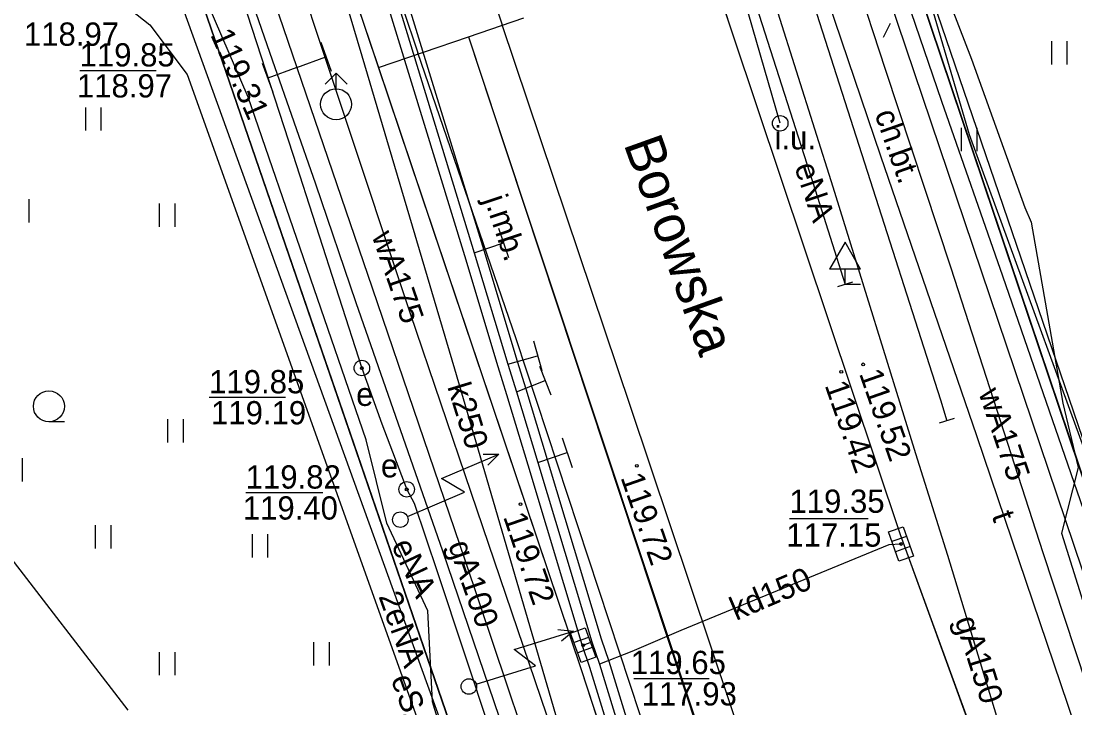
# Model space of a CAD drawing. Extents: x 6432121 to 6432331, y 5662538 to 5662686.
# Drawn here: x 6432243.57 to 6432277.55, y 5662605.46 to 5662627.61 of the extents above; entities that cross this region are included whole.
import ezdxf

# ---------------------------------------------------------------- set-up
doc = ezdxf.new("R2010")
doc.units = 0
for name, color, linetype in [('Warstwa 1', 7, 'Continuous'), ('Warstwa 10', 7, 'Continuous'), ('Warstwa 11', 7, 'Continuous'), ('Warstwa 12', 7, 'Continuous'), ('Warstwa 13', 7, 'Continuous'), ('Warstwa 14', 7, 'Continuous'), ('Warstwa 15', 7, 'Continuous'), ('Warstwa 19', 7, 'Continuous'), ('Warstwa 20', 7, 'Continuous'), ('Warstwa 24', 7, 'Continuous'), ('Warstwa 25', 7, 'Continuous'), ('Warstwa 31', 7, 'Continuous'), ('Warstwa 37', 7, 'Continuous'), ('Warstwa 4', 7, 'Continuous'), ('Warstwa 40', 7, 'Continuous'), ('Warstwa 5', 7, 'Continuous'), ('Warstwa 6', 7, 'Continuous'), ('Warstwa 61', 7, 'Continuous'), ('Warstwa 8', 7, 'Continuous'), ('Warstwa 9', 7, 'Continuous')]:
    doc.layers.add(name, color=color, linetype=linetype)

msp = doc.modelspace()

# ---------------------------------------------------------------- linework, layer by layer
at = {"layer": 'Warstwa 1'}
for p, q in [((6432267.75, 5662642.76), (6432287.64, 5662583.69)), ((6432267.75, 5662642.76), (6432287.64, 5662583.69)), ((6432246.69, 5662636.13), (6432263.163, 5662588.197)), ((6432246.69, 5662636.13), (6432263.163, 5662588.197))]:
    msp.add_line(p, q, dxfattribs=at)
for centre in [(6432255.8, 5662611.53), (6432258.012, 5662606.151)]:
    msp.add_circle(centre, 0.25, dxfattribs=at)
at = {"layer": 'Warstwa 10'}
msp.add_lwpolyline([(6432244.8, 5662632.18), (6432245.33, 5662629.54), (6432245.69, 5662629.01), (6432246.09, 5662628.79), (6432247.73, 5662627.49), (6432248.93, 5662625.88), (6432257.3, 5662602.44), (6432259.59, 5662595.58)], dxfattribs=at)
at = {"layer": 'Warstwa 12'}
for points in [[(6432260.149, 5662593.584), (6432259.505, 5662597.442), (6432258.113, 5662602.229), (6432246.261, 5662635.045), (6432242.6, 5662639.91), (6432237.105, 5662644.467), (6432235.235, 5662651.91), (6432228.3, 5662671.335), (6432227.148, 5662676.149), (6432227.614, 5662677.443), (6432228.191, 5662677.996), (6432231.551, 5662678.816), (6432233.235, 5662681.053)], [(6432259.267, 5662681.053), (6432259.329, 5662671.143), (6432259.331, 5662662.919), (6432260.078, 5662660.682), (6432263.877, 5662649.208), (6432267.527, 5662638.022), (6432271.438, 5662626.054), (6432273.548, 5662619.652), (6432276.516, 5662610.473), (6432279.664, 5662600.926), (6432282.613, 5662591.736), (6432284.976, 5662585.268), (6432286.395, 5662580.459), (6432288.268, 5662574.665)], [(6432288.269, 5662573.47), (6432290.18, 5662576.365), (6432289.651, 5662577.89), (6432283.657, 5662595.089), (6432278.636, 5662609.529), (6432275.228, 5662619.384), (6432273.259, 5662625.008), (6432269.06, 5662637.307), (6432265.455, 5662647.676), (6432262.131, 5662657.28), (6432261.494, 5662659.216), (6432262.228, 5662660.626), (6432262.598, 5662661.472), (6432263.21, 5662662.431), (6432263.592, 5662662.793), (6432265.636, 5662665.038), (6432264.282, 5662671.637), (6432263.631, 5662675.181), (6432263.032, 5662678.117), (6432262.911, 5662681.053)], [(6432251.161, 5662678.636), (6432251.195, 5662678.505), (6432250.722, 5662667.538), (6432250.449, 5662664.161), (6432250.95, 5662660.785), (6432251.946, 5662652.429), (6432252.859, 5662647.409), (6432253.435, 5662643.141), (6432255.033, 5662633.254), (6432255.483, 5662630.016), (6432258.492, 5662620.223), (6432259.57, 5662616.642), (6432259.85, 5662615.749), (6432260.538, 5662613.47), (6432262.28, 5662607.688), (6432262.524, 5662606.965), (6432264.736, 5662599.765)], [(6432264.124, 5662599.577), (6432261.914, 5662606.769), (6432261.67, 5662607.494), (6432259.926, 5662613.286), (6432259.238, 5662615.561), (6432258.958, 5662616.454), (6432257.88, 5662620.037), (6432254.857, 5662629.878), (6432254.401, 5662633.158), (6432252.801, 5662643.047), (6432252.227, 5662647.309), (6432251.312, 5662652.333), (6432250.316, 5662660.701), (6432249.805, 5662664.139), (6432250.084, 5662667.578), (6432250.551, 5662678.439), (6432250.541, 5662678.478)], [(6432258.356, 5662662.998), (6432258.39, 5662658.398), (6432260.508, 5662651.738), (6432262.768, 5662644.481), (6432265.197, 5662636.781), (6432267.384, 5662629.75), (6432269.748, 5662622.257), (6432272.462, 5662613.493), (6432273.441, 5662610.386), (6432276.081, 5662601.737), (6432278.642, 5662593.628), (6432281.263, 5662585.188), (6432283.543, 5662577.76), (6432283.852, 5662577.022), (6432284.284, 5662575.255)], [(6432261.338, 5662662.021), (6432260.831, 5662661.256), (6432261.33, 5662655.003), (6432261.566, 5662651.833), (6432262.397, 5662649.473), (6432263.18, 5662647.177), (6432265.745, 5662639.575), (6432268.331, 5662631.988), (6432271.28, 5662623.264), (6432274.385, 5662614.242), (6432277.778, 5662604.216), (6432280.796, 5662595.387), (6432284.518, 5662584.444), (6432287.071, 5662576.95), (6432288.269, 5662573.47)], [(6432244.451, 5662661.055), (6432244.51, 5662660.562), (6432244.747, 5662659.597), (6432247.148, 5662651.498), (6432250.159, 5662641.297), (6432254.564, 5662626.481), (6432257.548, 5662616.394), (6432260.807, 5662605.248), (6432262.453, 5662599.664), (6432266.272, 5662586.802), (6432268.265, 5662580.011), (6432268.423, 5662579.446)], [(6432243.958, 5662654.289), (6432246.621, 5662646.365), (6432250.032, 5662636.381), (6432251.998, 5662630.56), (6432253.864, 5662624.956), (6432256.122, 5662618.174), (6432258.071, 5662612.417), (6432261.076, 5662603.597), (6432261.907, 5662601.278), (6432263.382, 5662596.576), (6432264.52, 5662593.503), (6432265.328, 5662591.162), (6432268.156, 5662582.752), (6432268.733, 5662580.715)], [(6432243.16, 5662653.357), (6432252.465, 5662626.114), (6432254.893, 5662619.007), (6432257.883, 5662610.233), (6432261.03, 5662600.869), (6432263.754, 5662592.896), (6432267.107, 5662583.22), (6432267.857, 5662579.356), (6432269.061, 5662572.854)], [(6432294.644, 5662569.974), (6432292.199, 5662571.213), (6432291.73, 5662571.359), (6432291.554, 5662571.691), (6432290.843, 5662575.72), (6432287.011, 5662587.057), (6432285.41, 5662591.097), (6432281.352, 5662603.627), (6432279.346, 5662609.722), (6432279.211, 5662610.184), (6432279.026, 5662610.616), (6432274.158, 5662623.936), (6432272.237, 5662630.449), (6432265.984, 5662647.596), (6432266.37, 5662648.378)], [(6432291.73, 5662571.359), (6432291.68, 5662571.75), (6432289.74, 5662579), (6432288.94, 5662582.19), (6432279.33, 5662609.79), (6432279.211, 5662610.184), (6432278.94, 5662610.85), (6432266.32, 5662647.75), (6432266.37, 5662648.378)], [(6432268.05, 5662624.31), (6432264.48, 5662636.66)], [(6432244.8, 5662632.18), (6432245.33, 5662629.54), (6432245.69, 5662629.01), (6432246.09, 5662628.79), (6432247.73, 5662627.49), (6432248.93, 5662625.88), (6432257.3, 5662602.44), (6432259.59, 5662595.58)], [(6432268.23, 5662630.953), (6432270.582, 5662623.607), (6432273.222, 5662615.395), (6432273.419, 5662614.713)], [(6432266.467, 5662630.62), (6432269.173, 5662622.164), (6432270.14, 5662619.109)], [(6432249.61, 5662630.185), (6432250.286, 5662629.633), (6432252.331, 5662623.317), (6432254.562, 5662616.419), (6432255.202, 5662614.617), (6432256.008, 5662612.508), (6432256.249, 5662612.065), (6432256.997, 5662609.824), (6432258.713, 5662604.681), (6432261.287, 5662596.72), (6432264.864, 5662586.606), (6432264.777, 5662586.057)], [(6432264.921, 5662586.356), (6432264.864, 5662586.606), (6432260.124, 5662594.894), (6432256.835, 5662605.655), (6432256.691, 5662608.587), (6432255.365, 5662611.413), (6432254.697, 5662614.101), (6432250.901, 5662625.148), (6432249.199, 5662629.099), (6432249.05, 5662629.25)], [(6432273.378, 5662628.56), (6432274.214, 5662626.373), (6432275.936, 5662621.592), (6432276.137, 5662621.121), (6432277.158, 5662615.29), (6432277.656, 5662613.21), (6432277.121, 5662611.091), (6432279.065, 5662604.892), (6432281.714, 5662603.797), (6432281.489, 5662600.828), (6432283.129, 5662594.282), (6432283.903, 5662591.502), (6432284.529, 5662588.89)], [(6432271.946, 5662610.746), (6432271.557, 5662610.723), (6432264.842, 5662607.958), (6432263.268, 5662607.285), (6432262.219, 5662606.867)], [(6432261.697, 5662607.486), (6432261.975, 5662607.591)]]:
    msp.add_lwpolyline(points, dxfattribs=at)
at = {"layer": 'Warstwa 14'}
for p, q in [((6432245.464, 5662626.018), (6432247.927, 5662626.018)), ((6432249.641, 5662615.479), (6432252.104, 5662615.479)), ((6432250.822, 5662612.408), (6432253.307, 5662612.408)), ((6432268.354, 5662611.564), (6432270.891, 5662611.564)), ((6432263.331, 5662606.408), (6432265.757, 5662606.408))]:
    msp.add_line(p, q, dxfattribs=at)
for centre in [(6432254.562, 5662616.419), (6432254.562, 5662616.419), (6432256.008, 5662612.508), (6432256.008, 5662612.508), (6432271.946, 5662610.746), (6432271.946, 5662610.746), (6432261.697, 5662607.486), (6432261.697, 5662607.486)]:
    msp.add_circle(centre, 0.045, dxfattribs=at)
at = {"layer": 'Warstwa 19'}
for p, q in [((6432253.234, 5662626.926), (6432253.576, 5662625.986)), ((6432251.699, 5662625.3), (6432251.354, 5662626.238)), ((6432252.465, 5662626.114), (6432253.405, 5662626.456)), ((6432252.465, 5662626.114), (6432251.526, 5662625.769)), ((6432258.965, 5662620.932), (6432259.295, 5662619.988)), ((6432258.186, 5662620.13), (6432259.13, 5662620.46)), ((6432260.092, 5662617.3), (6432260.362, 5662616.337)), ((6432259.264, 5662616.548), (6432260.227, 5662616.818)), ((6432260.293, 5662616.485), (6432260.657, 5662615.554)), ((6432259.544, 5662615.655), (6432260.475, 5662616.02)), ((6432261.024, 5662614.167), (6432261.339, 5662613.218)), ((6432260.232, 5662613.378), (6432261.181, 5662613.693))]:
    msp.add_line(p, q, dxfattribs=at)
at = {"layer": 'Warstwa 20'}
for p, q in [((6432270.378, 5662619.185), (6432269.902, 5662619.033)), ((6432273.657, 5662614.789), (6432273.181, 5662614.637))]:
    msp.add_line(p, q, dxfattribs=at)
at = {"layer": 'Warstwa 24'}
msp.add_circle((6432268.05, 5662624.31), 0.25, dxfattribs=at)
at = {"layer": 'Warstwa 25'}
for centre in [(6432270.021, 5662616.3), (6432270.727, 5662616.538), (6432263.43, 5662613.264), (6432259.679, 5662612.028)]:
    msp.add_circle(centre, 0.045, dxfattribs=at)
at = {"layer": 'Warstwa 31'}
for p, q in [((6432270.64, 5662619.609), (6432270.14, 5662620.475)), ((6432270.14, 5662619.109), (6432270.14, 5662619.609)), ((6432270.64, 5662619.109), (6432270.14, 5662619.109))]:
    msp.add_line(p, q, dxfattribs=at)
for points in [[(6432270.14, 5662620.475), (6432269.64, 5662619.609)], [(6432270.64, 5662619.609), (6432269.64, 5662619.609)]]:
    msp.add_lwpolyline(points, dxfattribs=at)
at = {"layer": 'Warstwa 37'}
for points in [[(6432249.116, 5662650.415), (6432249.248, 5662649.722), (6432249.38, 5662649.03), (6432250.17, 5662645.84), (6432251.85, 5662640.08), (6432254.2, 5662633.06), (6432255.4, 5662629.47), (6432256.37, 5662626.58)], [(6432252.027, 5662650.548), (6432252.197, 5662649.798), (6432252.37, 5662649.049), (6432252.548, 5662648.301), (6432252.73, 5662647.555), (6432252.916, 5662646.809), (6432253.106, 5662646.064), (6432253.3, 5662645.32), (6432253.426, 5662644.858), (6432253.554, 5662644.396), (6432253.685, 5662643.935), (6432253.817, 5662643.474), (6432253.952, 5662643.014), (6432254.088, 5662642.555), (6432254.227, 5662642.096), (6432254.367, 5662641.638), (6432254.51, 5662641.18), (6432256.27, 5662635.89), (6432257.45, 5662632.38), (6432259.09, 5662627.49)], [(6432270.98, 5662592.032), (6432263.223, 5662615.178), (6432259.09, 5662627.49)], [(6432268.199, 5662591.096), (6432259.533, 5662617.358), (6432256.37, 5662626.58)]]:
    msp.add_lwpolyline(points, dxfattribs=at)
at = {"layer": 'Warstwa 4'}
for p, q in [((6432272.125, 5662610.993), (6432271.652, 5662610.829)), ((6432272.24, 5662610.663), (6432271.767, 5662610.499)), ((6432261.873, 5662607.735), (6432261.403, 5662607.566)), ((6432261.991, 5662607.406), (6432261.521, 5662607.237))]:
    msp.add_line(p, q, dxfattribs=at)
for points in [[(6432271.594, 5662627.529), (6432271.37, 5662627.082)], [(6432253.375, 5662625.57), (6432253.729, 5662625.924)], [(6432254.083, 5662625.57), (6432253.729, 5662625.924)], [(6432253.729, 5662625.424), (6432253.729, 5662625.924)]]:
    msp.add_lwpolyline(points, dxfattribs=at)
for points in [[(6432272.018, 5662611.3), (6432272.346, 5662610.355), (6432271.874, 5662610.192), (6432271.546, 5662611.137)], [(6432261.764, 5662608.041), (6432262.101, 5662607.1), (6432261.63, 5662606.931), (6432261.293, 5662607.872)]]:
    msp.add_lwpolyline(points, close=True, dxfattribs=at)
for centre, radius in [((6432253.729, 5662624.924), 0.5), ((6432254.562, 5662616.419), 0.25), ((6432256.008, 5662612.508), 0.25)]:
    msp.add_circle(centre, radius, dxfattribs=at)
at = {"layer": 'Warstwa 40'}
for points in [[(6432256.03, 5662611.628), (6432257.869, 5662612.414), (6432257.134, 5662612.861), (6432258.973, 5662613.647)], [(6432258.473, 5662613.647), (6432258.973, 5662613.647), (6432258.627, 5662613.287)], [(6432258.251, 5662606.226), (6432260.159, 5662606.823), (6432259.473, 5662607.342), (6432261.382, 5662607.939)], [(6432260.884, 5662607.989), (6432261.382, 5662607.939), (6432261.001, 5662607.615)]]:
    msp.add_lwpolyline(points, dxfattribs=at)
for centre in [(6432255.8, 5662611.53), (6432258.012, 5662606.151)]:
    msp.add_circle(centre, 0.25, dxfattribs=at)
at = {"layer": 'Warstwa 5'}
for p, q in [((6432271.072, 5662629.787), (6432281.622, 5662598.544)), ((6432250.664, 5662629.247), (6432251.67, 5662626.36)), ((6432276.805, 5662626.204), (6432276.805, 5662626.954)), ((6432277.305, 5662626.204), (6432277.305, 5662626.954)), ((6432251.67, 5662626.36), (6432253.062, 5662622.363)), ((6432245.657, 5662624.074), (6432245.657, 5662624.824)), ((6432246.157, 5662624.074), (6432246.157, 5662624.824)), ((6432273.899, 5662623.41), (6432273.899, 5662624.16)), ((6432274.399, 5662623.41), (6432274.399, 5662624.16)), ((6432253.062, 5662622.363), (6432254.367, 5662618.531)), ((6432243.834, 5662621.112), (6432243.834, 5662621.862)), ((6432248.038, 5662620.972), (6432248.038, 5662621.722)), ((6432248.538, 5662620.972), (6432248.538, 5662621.722)), ((6432254.367, 5662618.531), (6432257.161, 5662610.526)), ((6432248.306, 5662614.018), (6432248.306, 5662614.768)), ((6432248.806, 5662614.018), (6432248.806, 5662614.768)), ((6432243.622, 5662612.761), (6432243.622, 5662613.511)), ((6432241.266, 5662612.847), (6432247.012, 5662605.394)), ((6432245.977, 5662610.602), (6432245.977, 5662611.352)), ((6432246.477, 5662610.602), (6432246.477, 5662611.352)), ((6432251.032, 5662610.314), (6432251.032, 5662611.064)), ((6432251.532, 5662610.314), (6432251.532, 5662611.064)), ((6432257.161, 5662610.526), (6432259.889, 5662602.532)), ((6432253.013, 5662606.826), (6432253.013, 5662607.576)), ((6432253.513, 5662606.826), (6432253.513, 5662607.576)), ((6432248.039, 5662606.514), (6432248.039, 5662607.264)), ((6432248.539, 5662606.514), (6432248.539, 5662607.264))]:
    msp.add_line(p, q, dxfattribs=at)
at = {"layer": 'Warstwa 6'}
msp.add_line((6432244.97, 5662614.686), (6432244.47, 5662614.686), dxfattribs=at)
for points in [[(6432278.892, 5662645.679), (6432279.29, 5662646.39), (6432267.75, 5662642.76), (6432287.64, 5662583.69), (6432294.025, 5662578.332), (6432295.024, 5662576.599), (6432295.196, 5662575.127), (6432301.46, 5662572.69), (6432295.88, 5662579.43), (6432289.26, 5662614.9)], [(6432259.074, 5662585.787), (6432263.163, 5662588.197), (6432246.69, 5662636.13), (6432228.29, 5662630.34), (6432193.86, 5662619.79), (6432180.9, 5662615.82)]]:
    msp.add_lwpolyline(points, close=True, dxfattribs=at)
for points in [[(6432295.199, 5662556.053), (6432289.811, 5662577.223), (6432287.64, 5662583.69), (6432267.75, 5662642.76), (6432246.69, 5662636.13), (6432263.163, 5662588.197), (6432269.007, 5662560.534), (6432269.756, 5662556.053)], [(6432261.53, 5662642.45), (6432261.725, 5662641.888), (6432263.054, 5662637.661), (6432266.526, 5662627.159), (6432271.921, 5662611.052), (6432274.366, 5662604.334), (6432277.03, 5662595.697), (6432280.318, 5662586.138), (6432281.64, 5662582.902)], [(6432253.68, 5662630.32), (6432261.638, 5662606.697), (6432266.51, 5662591.804), (6432267.797, 5662587.848)], [(6432257.996, 5662627.099), (6432261.912, 5662615.276), (6432267.276, 5662599.098), (6432269.793, 5662591.641)]]:
    msp.add_lwpolyline(points, dxfattribs=at)
msp.add_circle((6432244.47, 5662615.186), 0.5, dxfattribs=at)
at = {"layer": 'Warstwa 61'}
msp.add_lwpolyline([(6432250.819, 5662681.053), (6432250.821, 5662679.711), (6432250.716, 5662679.086), (6432250.873, 5662678.472), (6432250.403, 5662667.558), (6432250.127, 5662664.15), (6432250.633, 5662660.743), (6432251.629, 5662652.381), (6432252.543, 5662647.359), (6432253.118, 5662643.094), (6432254.717, 5662633.206), (6432255.17, 5662629.947), (6432255.2, 5662629.93), (6432258.186, 5662620.13), (6432259.264, 5662616.548), (6432259.544, 5662615.655), (6432260.232, 5662613.378), (6432261.975, 5662607.591), (6432262.219, 5662606.867), (6432264.43, 5662599.671)], dxfattribs=at)
at = {"layer": 'Warstwa 8'}
for p, q in [((6432253.68, 5662630.32), (6432255.099, 5662626.107)), ((6432266.179, 5662628.209), (6432266.526, 5662627.159)), ((6432257.996, 5662627.099), (6432259.78, 5662627.71)), ((6432257.996, 5662627.099), (6432259.78, 5662627.71)), ((6432255.099, 5662626.107), (6432257.996, 5662627.099)), ((6432255.099, 5662626.107), (6432257.996, 5662627.099)), ((6432257.996, 5662627.099), (6432258.72, 5662624.914)), ((6432257.996, 5662627.099), (6432258.72, 5662624.914)), ((6432266.526, 5662627.159), (6432271.921, 5662611.052)), ((6432255.099, 5662626.107), (6432261.638, 5662606.697)), ((6432258.72, 5662624.914), (6432261.912, 5662615.276)), ((6432258.72, 5662624.914), (6432269.793, 5662591.641)), ((6432261.912, 5662615.276), (6432267.276, 5662599.098)), ((6432271.921, 5662611.052), (6432274.366, 5662604.334)), ((6432261.638, 5662606.697), (6432266.51, 5662591.804))]:
    msp.add_line(p, q, dxfattribs=at)
at = {"layer": 'Warstwa 9'}
for p, q in [((6432253.68, 5662630.32), (6432261.638, 5662606.697)), ((6432271.072, 5662629.787), (6432281.622, 5662598.544)), ((6432250.664, 5662629.247), (6432251.67, 5662626.36)), ((6432266.179, 5662628.209), (6432266.526, 5662627.159)), ((6432266.526, 5662627.159), (6432271.921, 5662611.052)), ((6432251.67, 5662626.36), (6432253.062, 5662622.363)), ((6432253.062, 5662622.363), (6432254.367, 5662618.531)), ((6432254.367, 5662618.531), (6432257.161, 5662610.526)), ((6432241.266, 5662612.847), (6432247.012, 5662605.394)), ((6432271.921, 5662611.052), (6432274.366, 5662604.334)), ((6432257.161, 5662610.526), (6432259.889, 5662602.532)), ((6432261.638, 5662606.697), (6432266.51, 5662591.804))]:
    msp.add_line(p, q, dxfattribs=at)

# ---------------------------------------------------------------- texts
at = {"layer": 'Warstwa 11'}
msp.add_text('eSA', height=0.75, rotation=289.6531, dxfattribs=at).set_placement((6432255.489, 5662606.397))
at = {"layer": 'Warstwa 13'}
for s, rotation, p in [('eNA', 288.4384, (6432268.499, 5662622.914)), ('wA175', 289.1088, (6432254.872, 5662620.688)), ('k250', 286.9946, (6432257.31, 5662615.822)), ('wA175', 288.6218, (6432274.438, 5662615.626)), ('t', 289.3895, (6432274.86, 5662611.664)), ('eNA', 295.1363, (6432255.498, 5662610.707)), ('gA100', 289.2749, (6432257.334, 5662610.717)), ('kd150', 23.136, (6432266.627, 5662608.264)), ('2eNA', 289.8593, (6432255.09, 5662609.063)), ('gA150', 287.6706, (6432273.671, 5662608.295))]:
    msp.add_text(s, height=0.75, rotation=rotation, dxfattribs=at).set_placement(p)
at = {"layer": 'Warstwa 14'}
for s, p in [('118.97', (6432243.665, 5662626.811)), ('118.97', (6432245.373, 5662625.143)), ('119.19', (6432249.698, 5662614.604)), ('119.40', (6432250.723, 5662611.533)), ('117.15', (6432268.248, 5662610.66)), ('117.93', (6432263.586, 5662605.539))]:
    msp.add_text(s, height=0.75, dxfattribs=at).set_placement(p)
for s, height, rotation, p in [('119.31', 0.75, 294.0018, (6432249.666, 5662627.169)), ('Borowska', 1.25, 289.7245, (6432262.994, 5662623.646))]:
    msp.add_text(s, height=height, rotation=rotation, dxfattribs=at).set_placement(p)
at = {"layer": 'Warstwa 15'}
for s, p in [('119.85', (6432245.46, 5662626.143)), ('119.85', (6432249.637, 5662615.604)), ('119.82', (6432250.816, 5662612.533)), ('119.35', (6432268.349, 5662611.751)), ('119.65', (6432263.232, 5662606.553))]:
    msp.add_text(s, height=0.75, dxfattribs=at).set_placement(p)
at = {"layer": 'Warstwa 24'}
msp.add_text('i.u.', height=0.75, dxfattribs=at).set_placement((6432267.867, 5662623.471))
at = {"layer": 'Warstwa 25'}
for s, rotation, p in [('119.52', 289.2749, (6432270.587, 5662616.245)), ('119.42', 289.2749, (6432269.478, 5662615.865)), ('119.72', 289.2234, (6432262.895, 5662612.896)), ('119.72', 288.6561, (6432259.112, 5662611.627))]:
    msp.add_text(s, height=0.75, rotation=rotation, dxfattribs=at).set_placement(p)
at = {"layer": 'Warstwa 5'}
for p in [(6432254.378, 5662615.198), (6432255.176, 5662612.894)]:
    msp.add_text('e', height=0.75, dxfattribs=at).set_placement(p)
at = {"layer": 'Warstwa 8'}
msp.add_text('j.mb.', height=0.75, rotation=288.4098, dxfattribs=at).set_placement((6432258.502, 5662621.864))
at = {"layer": 'Warstwa 9'}
msp.add_text('ch.bt.', height=0.75, rotation=289.401, dxfattribs=at).set_placement((6432271.084, 5662624.617))

doc.saveas('drawing.dxf')
